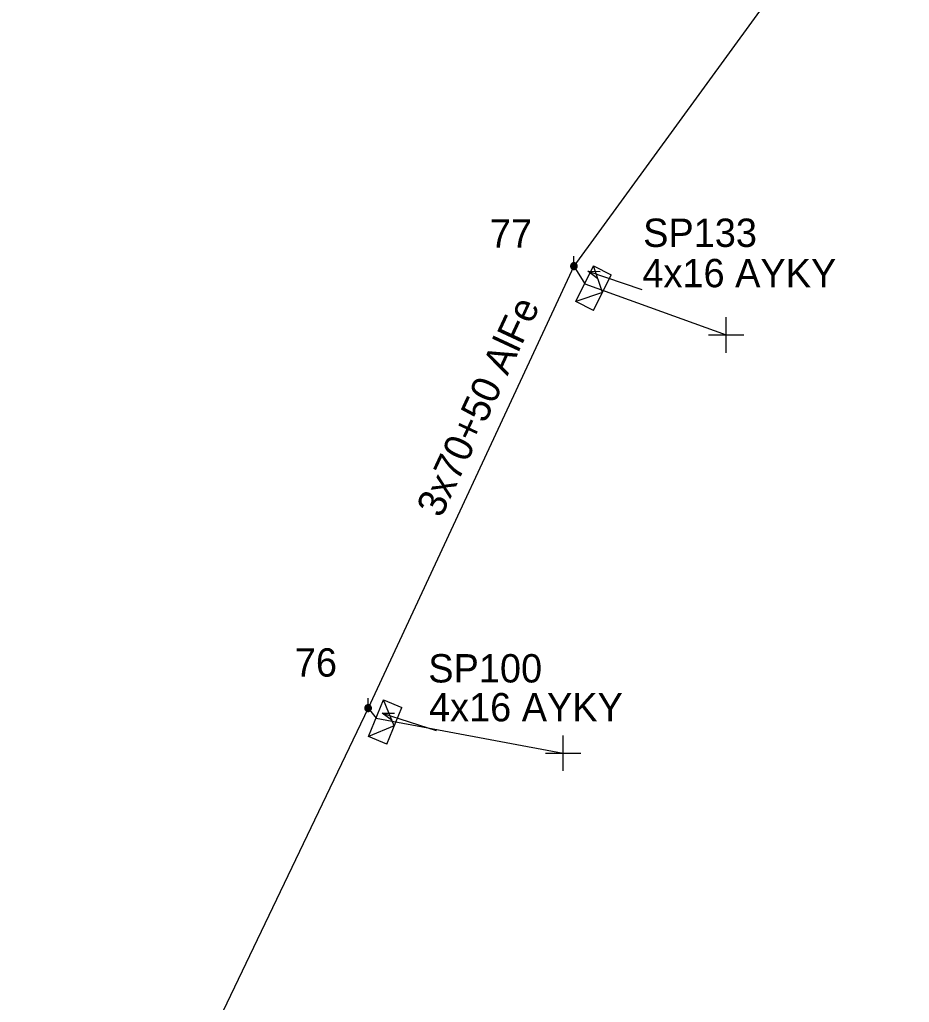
# Model space of a CAD drawing. Extents: x -788458 to -786145, y -1154772 to -1152372.
# Drawn here: x -787223.86 to -787192.48, y -1152557.42 to -1152522.76 of the extents above; entities that cross this region are included whole.
import ezdxf

# ---------------------------------------------------------------- set-up
doc = ezdxf.new("R2010")
doc.units = 0
for name, color, linetype in [('Vrstva 1', 7, 'Continuous'), ('Vrstva 13', 7, 'Continuous'), ('Vrstva 14', 7, 'Continuous'), ('Vrstva 2', 7, 'Continuous'), ('Vrstva 31', 7, 'Continuous'), ('Vrstva 33', 7, 'Continuous'), ('Vrstva 34', 7, 'Continuous'), ('Vrstva 52', 7, 'Continuous'), ('Vrstva 54', 7, 'Continuous'), ('Vrstva 59', 7, 'Continuous'), ('Vrstva 9', 7, 'Continuous')]:
    doc.layers.add(name, color=color, linetype=linetype)

# ---------------------------------------------------------------- blocks, each defined once
blk = doc.blocks.new('NN565')
at = {"layer": 'Vrstva 2'}
for points in [[(0.015, 0.528), (0.015, 2.528)], [(0.157, 0.937), (0.015, 0.528), (-0.119, 0.937)]]:
    blk.add_lwpolyline(points, dxfattribs=at)
blk = doc.blocks.new('NN800')
at = {"layer": 'Vrstva 1'}
for points in [[(-0.442, 0.442), (0.442, -0.442)], [(-0.442, -0.442), (0.442, 0.442)]]:
    blk.add_lwpolyline(points, dxfattribs=at)
blk = doc.blocks.new('NN630')
at = {"layer": 'Vrstva 9'}
for points in [[(-0.003, -0.7), (-0.703, 0)], [(-0.703, -0.7), (-0.703, 0), (0.697, 0), (0.697, -0.7)], [(-0.003, -0.7), (0.697, 0)], [(-0.703, -0.7), (0.697, -0.7)]]:
    blk.add_lwpolyline(points, dxfattribs=at)
blk = doc.blocks.new('NN500')
at = {"layer": 'Vrstva 2'}
for points in [[(-0.001, -0.235), (0.023, -0.234), (0.048, -0.23), (0.071, -0.224), (0.094, -0.215), (0.116, -0.204), (0.137, -0.191), (0.156, -0.175), (0.173, -0.158), (0.189, -0.139), (0.202, -0.118), (0.213, -0.096), (0.222, -0.073), (0.229, -0.049), (0.232, -0.025), (0.234, 0), (0.232, 0.024), (0.229, 0.048), (0.222, 0.072), (0.213, 0.095), (0.202, 0.117), (0.189, 0.138), (0.173, 0.157), (0.156, 0.174), (0.137, 0.19), (0.116, 0.203), (0.094, 0.214), (0.071, 0.223), (0.048, 0.229), (0.023, 0.233), (-0.001, 0.235), (-0.026, 0.233), (-0.05, 0.229), (-0.074, 0.223), (-0.097, 0.214), (-0.119, 0.203), (-0.139, 0.19), (-0.158, 0.174), (-0.176, 0.157), (-0.191, 0.138), (-0.205, 0.117), (-0.216, 0.095), (-0.225, 0.072), (-0.231, 0.048), (-0.235, 0.024), (-0.236, 0), (-0.235, -0.025), (-0.231, -0.049), (-0.225, -0.073), (-0.216, -0.096), (-0.205, -0.118), (-0.191, -0.139), (-0.176, -0.158), (-0.158, -0.175), (-0.139, -0.191), (-0.119, -0.204), (-0.097, -0.215), (-0.074, -0.224), (-0.05, -0.23), (-0.026, -0.234), (-0.001, -0.235)], [(-0.001, -0.235), (0.023, -0.234), (0.048, -0.23), (0.071, -0.224), (0.094, -0.215), (0.116, -0.204), (0.137, -0.191), (0.156, -0.175), (0.173, -0.158), (0.189, -0.139), (0.202, -0.118), (0.213, -0.096), (0.222, -0.073), (0.229, -0.049), (0.232, -0.025), (0.234, 0), (0.232, 0.024), (0.229, 0.048), (0.222, 0.072), (0.213, 0.095), (0.202, 0.117), (0.189, 0.138), (0.173, 0.157), (0.156, 0.174), (0.137, 0.19), (0.116, 0.203), (0.094, 0.214), (0.071, 0.223), (0.048, 0.229), (0.023, 0.233), (-0.001, 0.235), (-0.026, 0.233), (-0.05, 0.229), (-0.074, 0.223), (-0.097, 0.214), (-0.119, 0.203), (-0.139, 0.19), (-0.158, 0.174), (-0.176, 0.157), (-0.191, 0.138), (-0.205, 0.117), (-0.216, 0.095), (-0.225, 0.072), (-0.231, 0.048), (-0.235, 0.024), (-0.236, 0), (-0.235, -0.025), (-0.231, -0.049), (-0.225, -0.073), (-0.216, -0.096), (-0.205, -0.118), (-0.191, -0.139), (-0.176, -0.158), (-0.158, -0.175), (-0.139, -0.191), (-0.119, -0.204), (-0.097, -0.215), (-0.074, -0.224), (-0.05, -0.23), (-0.026, -0.234), (-0.001, -0.235)], [(-0.001, -0.206), (0.02, -0.205), (0.041, -0.201), (0.062, -0.196), (0.082, -0.188), (0.101, -0.178), (0.12, -0.167), (0.136, -0.153), (0.151, -0.138), (0.165, -0.121), (0.177, -0.103), (0.186, -0.084), (0.194, -0.064), (0.2, -0.043), (0.203, -0.022), (0.204, 0), (0.203, 0.021), (0.2, 0.042), (0.194, 0.063), (0.186, 0.083), (0.177, 0.102), (0.165, 0.12), (0.151, 0.137), (0.136, 0.152), (0.12, 0.166), (0.101, 0.177), (0.082, 0.187), (0.062, 0.195), (0.041, 0.2), (0.02, 0.204), (-0.001, 0.205), (-0.023, 0.204), (-0.044, 0.2), (-0.065, 0.195), (-0.085, 0.187), (-0.104, 0.177), (-0.122, 0.166), (-0.139, 0.152), (-0.154, 0.137), (-0.167, 0.12), (-0.179, 0.102), (-0.189, 0.083), (-0.197, 0.063), (-0.202, 0.042), (-0.205, 0.021), (-0.207, 0), (-0.205, -0.022), (-0.202, -0.043), (-0.197, -0.064), (-0.189, -0.084), (-0.179, -0.103), (-0.167, -0.121), (-0.154, -0.138), (-0.139, -0.153), (-0.122, -0.167), (-0.104, -0.178), (-0.085, -0.188), (-0.065, -0.196), (-0.044, -0.201), (-0.023, -0.205), (-0.001, -0.206)], [(-0.001, -0.176), (0.017, -0.175), (0.035, -0.172), (0.053, -0.168), (0.07, -0.161), (0.087, -0.153), (0.102, -0.143), (0.116, -0.131), (0.129, -0.118), (0.141, -0.104), (0.151, -0.088), (0.159, -0.072), (0.166, -0.055), (0.171, -0.037), (0.174, -0.019), (0.175, 0), (0.174, 0.018), (0.171, 0.036), (0.166, 0.054), (0.159, 0.071), (0.151, 0.087), (0.141, 0.103), (0.129, 0.117), (0.116, 0.13), (0.102, 0.142), (0.087, 0.152), (0.07, 0.16), (0.053, 0.167), (0.035, 0.172), (0.017, 0.174), (-0.001, 0.175), (-0.02, 0.174), (-0.038, 0.172), (-0.056, 0.167), (-0.073, 0.16), (-0.089, 0.152), (-0.105, 0.142), (-0.119, 0.13), (-0.132, 0.117), (-0.143, 0.103), (-0.153, 0.087), (-0.162, 0.071), (-0.168, 0.054), (-0.173, 0.036), (-0.176, 0.018), (-0.177, 0), (-0.176, -0.019), (-0.173, -0.037), (-0.168, -0.055), (-0.162, -0.072), (-0.153, -0.088), (-0.143, -0.104), (-0.132, -0.118), (-0.119, -0.131), (-0.105, -0.143), (-0.089, -0.153), (-0.073, -0.161), (-0.056, -0.168), (-0.038, -0.172), (-0.02, -0.175), (-0.001, -0.176)], [(-0.001, -0.147), (0.014, -0.146), (0.029, -0.143), (0.044, -0.139), (0.058, -0.134), (0.072, -0.127), (0.085, -0.119), (0.097, -0.109), (0.107, -0.098), (0.117, -0.086), (0.125, -0.073), (0.132, -0.06), (0.138, -0.046), (0.142, -0.031), (0.144, -0.016), (0.145, 0), (0.144, 0.015), (0.142, 0.03), (0.138, 0.045), (0.132, 0.059), (0.125, 0.073), (0.117, 0.086), (0.107, 0.097), (0.097, 0.108), (0.085, 0.118), (0.072, 0.126), (0.058, 0.133), (0.044, 0.139), (0.029, 0.143), (0.014, 0.145), (-0.001, 0.146), (-0.017, 0.145), (-0.032, 0.143), (-0.046, 0.139), (-0.061, 0.133), (-0.074, 0.126), (-0.087, 0.118), (-0.099, 0.108), (-0.11, 0.097), (-0.119, 0.086), (-0.128, 0.073), (-0.135, 0.059), (-0.14, 0.045), (-0.144, 0.03), (-0.147, 0.015), (-0.147, 0), (-0.147, -0.016), (-0.144, -0.031), (-0.14, -0.046), (-0.135, -0.06), (-0.128, -0.073), (-0.119, -0.086), (-0.11, -0.098), (-0.099, -0.109), (-0.087, -0.119), (-0.074, -0.127), (-0.061, -0.134), (-0.046, -0.139), (-0.032, -0.143), (-0.017, -0.146), (-0.001, -0.147)], [(-0.001, -0.117), (0.011, -0.116), (0.023, -0.114), (0.035, -0.111), (0.046, -0.107), (0.057, -0.101), (0.067, -0.095), (0.077, -0.087), (0.085, -0.078), (0.093, -0.069), (0.1, -0.059), (0.105, -0.048), (0.11, -0.036), (0.113, -0.025), (0.115, -0.013), (0.115, 0), (0.115, 0.012), (0.113, 0.024), (0.11, 0.036), (0.105, 0.047), (0.1, 0.058), (0.093, 0.068), (0.085, 0.078), (0.077, 0.086), (0.067, 0.094), (0.057, 0.101), (0.046, 0.106), (0.035, 0.11), (0.023, 0.114), (0.011, 0.116), (-0.001, 0.116), (-0.013, 0.116), (-0.025, 0.114), (-0.037, 0.11), (-0.049, 0.106), (-0.059, 0.101), (-0.07, 0.094), (-0.079, 0.086), (-0.088, 0.078), (-0.096, 0.068), (-0.102, 0.058), (-0.108, 0.047), (-0.112, 0.036), (-0.115, 0.024), (-0.117, 0.012), (-0.118, 0), (-0.117, -0.013), (-0.115, -0.025), (-0.112, -0.036), (-0.108, -0.048), (-0.102, -0.059), (-0.096, -0.069), (-0.088, -0.078), (-0.079, -0.087), (-0.07, -0.095), (-0.059, -0.101), (-0.049, -0.107), (-0.037, -0.111), (-0.025, -0.114), (-0.013, -0.116), (-0.001, -0.117)], [(-0.001, -0.087), (0.008, -0.087), (0.017, -0.085), (0.026, -0.083), (0.034, -0.08), (0.042, -0.076), (0.05, -0.071), (0.057, -0.065), (0.063, -0.059), (0.069, -0.051), (0.074, -0.044), (0.078, -0.036), (0.081, -0.027), (0.084, -0.019), (0.085, -0.01), (0.086, 0), (0.085, 0.009), (0.084, 0.018), (0.081, 0.026), (0.078, 0.035), (0.074, 0.043), (0.069, 0.051), (0.063, 0.058), (0.057, 0.064), (0.05, 0.07), (0.042, 0.075), (0.034, 0.079), (0.026, 0.082), (0.017, 0.085), (0.008, 0.086), (-0.001, 0.087), (-0.01, 0.086), (-0.019, 0.085), (-0.028, 0.082), (-0.037, 0.079), (-0.045, 0.075), (-0.052, 0.07), (-0.059, 0.064), (-0.066, 0.058), (-0.072, 0.051), (-0.077, 0.043), (-0.081, 0.035), (-0.084, 0.026), (-0.086, 0.018), (-0.088, 0.009), (-0.088, 0), (-0.088, -0.01), (-0.086, -0.019), (-0.084, -0.027), (-0.081, -0.036), (-0.077, -0.044), (-0.072, -0.052), (-0.066, -0.059), (-0.059, -0.065), (-0.052, -0.071), (-0.045, -0.076), (-0.037, -0.08), (-0.028, -0.083), (-0.019, -0.085), (-0.01, -0.087), (-0.001, -0.087)], [(-0.001, -0.058), (0.005, -0.057), (0.011, -0.056), (0.016, -0.055), (0.022, -0.053), (0.027, -0.05), (0.032, -0.047), (0.037, -0.043), (0.041, -0.039), (0.045, -0.034), (0.048, -0.029), (0.051, -0.024), (0.053, -0.018), (0.055, -0.012), (0.056, -0.006), (0.056, 0), (0.056, 0.006), (0.055, 0.011), (0.053, 0.017), (0.051, 0.023), (0.048, 0.028), (0.045, 0.033), (0.041, 0.038), (0.037, 0.042), (0.032, 0.046), (0.027, 0.049), (0.022, 0.052), (0.016, 0.054), (0.011, 0.056), (0.005, 0.057), (-0.001, 0.057), (-0.007, 0.057), (-0.013, 0.056), (-0.019, 0.054), (-0.025, 0.052), (-0.03, 0.049), (-0.035, 0.046), (-0.04, 0.042), (-0.044, 0.038), (-0.048, 0.033), (-0.051, 0.028), (-0.054, 0.023), (-0.056, 0.017), (-0.057, 0.011), (-0.058, 0.006), (-0.059, 0), (-0.058, -0.006), (-0.057, -0.012), (-0.056, -0.018), (-0.054, -0.024), (-0.051, -0.029), (-0.048, -0.034), (-0.044, -0.039), (-0.04, -0.043), (-0.035, -0.047), (-0.03, -0.05), (-0.025, -0.053), (-0.019, -0.055), (-0.013, -0.056), (-0.007, -0.057), (-0.001, -0.058)], [(-0.001, -0.028), (0.002, -0.028), (0.005, -0.028), (0.007, -0.027), (0.01, -0.026), (0.013, -0.024), (0.015, -0.023), (0.017, -0.021), (0.019, -0.019), (0.021, -0.017), (0.023, -0.014), (0.024, -0.012), (0.025, -0.009), (0.026, -0.006), (0.026, -0.003), (0.027, 0), (0.026, 0.002), (0.026, 0.005), (0.025, 0.008), (0.024, 0.011), (0.023, 0.013), (0.021, 0.016), (0.019, 0.018), (0.017, 0.02), (0.015, 0.022), (0.013, 0.024), (0.01, 0.025), (0.007, 0.026), (0.005, 0.027), (0.002, 0.027), (-0.001, 0.027), (-0.004, 0.027), (-0.007, 0.027), (-0.01, 0.026), (-0.012, 0.025), (-0.015, 0.024), (-0.018, 0.022), (-0.02, 0.02), (-0.022, 0.018), (-0.024, 0.016), (-0.025, 0.013), (-0.027, 0.011), (-0.028, 0.008), (-0.028, 0.005), (-0.029, 0.002), (-0.029, 0), (-0.029, -0.003), (-0.028, -0.006), (-0.028, -0.009), (-0.027, -0.012), (-0.025, -0.014), (-0.024, -0.017), (-0.022, -0.019), (-0.02, -0.021), (-0.018, -0.023), (-0.015, -0.024), (-0.012, -0.026), (-0.01, -0.027), (-0.007, -0.028), (-0.004, -0.028), (-0.001, -0.028)], [(0.234, 0), (0.704, 0)]]:
    blk.add_lwpolyline(points, dxfattribs=at)

msp = doc.modelspace()

# ---------------------------------------------------------------- linework, layer by layer
at = {"layer": 'Vrstva 1'}
msp.add_lwpolyline([(-787192.479, -1152515.179), (-787204.31, -1152531.45), (-787211.57, -1152547.04), (-787217.9, -1152560.27), (-787220.49, -1152567.22), (-787223.86, -1152575.79)], dxfattribs=at)
at = {"layer": 'Vrstva 52'}
for points in [[(-787204.31, -1152531.45), (-787203.93, -1152532.07)], [(-787211.57, -1152547.04), (-787211.29, -1152547.39)]]:
    msp.add_lwpolyline(points, dxfattribs=at)
at = {"layer": 'Vrstva 59'}
for points in [[(-787203.93, -1152532.07), (-787198.94, -1152533.88)], [(-787211.29, -1152547.39), (-787204.69, -1152548.63)]]:
    msp.add_lwpolyline(points, dxfattribs=at)

# ---------------------------------------------------------------- block references
at = {"layer": 'Vrstva 13', "xscale": 0.5, "yscale": 0.5, "rotation": 90}
for p in [(-787204.31, -1152531.45), (-787211.57, -1152547.04)]:
    msp.add_blockref('NN500', p, dxfattribs=at)
at = {"layer": 'Vrstva 13'}
for p, rotation in [((-787204.31, -1152531.45), -108.59849453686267), ((-787211.57, -1152547.04), -107.81388047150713)]:
    msp.add_blockref('NN565', p, dxfattribs=dict(at, rotation=rotation))
at = {"layer": 'Vrstva 31'}
for p, rotation in [((-787203.93, -1152532.07), 63.43494882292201), ((-787211.29, -1152547.39), 67.40540889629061)]:
    msp.add_blockref('NN630', p, dxfattribs=dict(at, rotation=rotation))
at = {"layer": 'Vrstva 34', "rotation": 44.99999995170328}
for p in [(-787198.94, -1152533.88), (-787204.69, -1152548.63)]:
    msp.add_blockref('NN800', p, dxfattribs=at)

# ---------------------------------------------------------------- texts
at = {"layer": 'Vrstva 14'}
for s, p in [('77', (-787207.275, -1152530.8)), ('76', (-787214.155, -1152545.93))]:
    msp.add_text(s, height=1, dxfattribs=at).set_placement(p)
at = {"layer": 'Vrstva 2'}
msp.add_text('3x70+50 AlFe', height=1, rotation=65.029, dxfattribs=at).set_placement((-787208.994, -1152540.365))
at = {"layer": 'Vrstva 33'}
for s, p in [('SP133', (-787201.869, -1152530.774)), ('SP100', (-787209.447, -1152546.137))]:
    msp.add_text(s, height=1, dxfattribs=at).set_placement(p)
at = {"layer": 'Vrstva 54'}
for p in [(-787201.895, -1152532.196), (-787209.422, -1152547.508)]:
    msp.add_text('4x16 AYKY', height=1, dxfattribs=at).set_placement(p)

doc.saveas('drawing.dxf')
